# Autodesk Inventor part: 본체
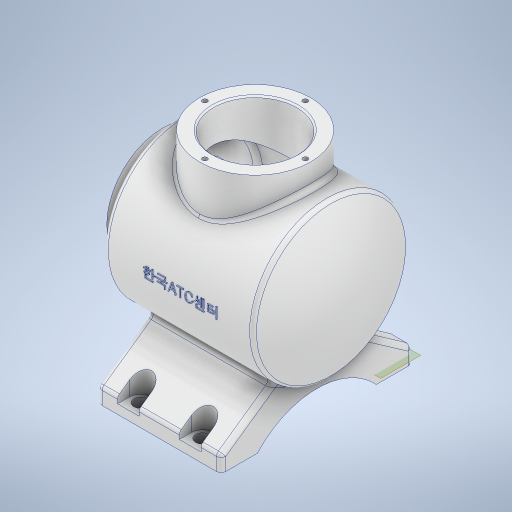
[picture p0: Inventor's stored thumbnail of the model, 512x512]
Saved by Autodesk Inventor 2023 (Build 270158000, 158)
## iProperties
Created: 2023-12
Part Number: 본체
Material: 알루미늄 6061
Document SubType Name: Modeling
Designer: asung
Mass: 1296.69 g
Surface Area: 1060.45 cm^2
Volume: 480.256 cm^3
Density: 2.7 g/cm^3
Appearance: 알루미늄 - 평지
Author: asung
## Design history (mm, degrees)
sketch "스케치1"
  geometry: L1 (60, 0)-(-60, 0); L2 (-60, 0)-(-60, 36); L3 (-60, 36)-(-48, 36); L4 (-48, 36)-(-48, 50); L5 (-48, 50)-(48.336, 50); L6 (-41, 43)-(43.887, 43); L7 (-41, 27)-(-41, 43); L8 (-60, 0)-(-60, 27); L9 (-60, 27)-(-41, 27); A1 r 113 centre (-53, 0) between (60, 0) and (48.336, 50); A2 r 106 centre (-53, 0) between (53, 0) and (43.887, 43); 2 further points
  constraints: 18 end point, 4 perpendicular, 4 point on circle, 2 centre point, 1 horizontal, 1 point on line, 1 vertical
  dimensions: "d3" = 120 distance of L1.start L1.end; "d4" = 36 distance of L1.end L2.end; "d5" = 12 distance of L2.end L3.end; "d6" = 14 distance of L3.end L4.end; "d13" = 7 distance between parallel lines of L5 L6; "d15" = 27 distance of L1.end L8.end; "d16" = 19 distance of L7.start L8.end
revolve "회전1" sketch "스케치1" stored, may be unused: angle "d17" = 360 deg
fillet "모깎기3" dims "d20" = 3
fillet "모깎기4" dims "d21" = 3
chamfer "모따기1" distance "d22" = 1; stored, may be unused: second distance "d23" = 2, angle "d24" = 45 deg
node "작업 평면1"
sketch "스케치2"
  geometry: C1 r 36 at (0, 0); 1 further point
  constraints: 1 centre point, 1 coincident
  dimensions: "d26" = 72 diameter of C1
extrude "돌출1" join sketch "스케치2" stored distance "d27" = 10; taper "d28" = 0 deg
fillet "모깎기5" dims "d29" = 3
sketch "스케치3"
  geometry: C1 r 27 at (0, 0); 1 further point
  constraints: 1 centre point, 1 coincident
  dimensions: "d30" = 54 diameter of C1
extrude "돌출2" cut sketch "스케치3" stored distance "d31" = 10; taper "d32" = 0 deg
chamfer "모따기2" distance "d33" = 1; stored, may be unused: second distance "d34" = 2, angle "d35" = 45 deg
sketch "스케치4" dims "d36" = 65
  geometry: 3 further points
  constraints: 1 coincident, 1 vertical alignment, 2 other
hole "구멍1" sketch "스케치4" at (0, 32.5) diameter "d37" = 3.242; stored, may be unused: countersink angle "d41" = 90 deg, drill point angle "d43" = 118 deg; dims "d38" = 8, "d39" = 4, "d40" = 2, "d42" = 10
sketch "스케치5" dims "d47" = 65
  geometry: 3 further points
  constraints: 1 coincident, 1 vertical alignment, 2 other
hole "구멍2" sketch "스케치5" at (0, 32.5) diameter "d48" = 3.242; stored, may be unused: countersink angle "d52" = 90 deg, drill point angle "d54" = 118 deg; dims "d49" = 8, "d50" = 4, "d51" = 2, "d53" = 10
sketch "스케치6"
  geometry: L1 (35.889, 36)-(65, 36) reference; L2 (65, 36)-(65, 34.121) reference; L3 (65, 34.121)-(55, 34.121) reference; L4 (55, 34.121)-(54.026, 32.5) reference; L5 (54.026, 32.5)-(55, 30.879) reference; L6 (55, 30.879)-(65, 30.879) reference; L7 (65, 30.879)-(65, 28) reference; L8 (65, 28)-(64, 27) reference; L9 (64, 27)-(33.466, 27) reference; L10 (33.466, -27)-(64, -27) reference; L11 (64, -27)-(65, -28) reference; L12 (65, -28)-(65, -30.879) reference; L13 (65, -30.879)-(55, -30.879) reference; L14 (55, -30.879)-(54.026, -32.5) reference; L15 (54.026, -32.5)-(55, -34.121) reference; L16 (55, -34.121)-(65, -34.121) reference; L17 (65, -34.121)-(65, -36) reference; L18 (65, -36)-(35.889, -36) reference; L19 (0, 0)-(-77, 0); L20 (-77, 0)-(-77, 38.5); L21 (-77, 38.5)-(-77, 62); L22 (-77, 62)-(-67, 62); L23 (-67, 62)-(-42.278, 26.694); L24 (-77, 0)-(-77, -38.5); L25 (-77, -38.5)-(-77, -62); L26 (-77, -62)-(-67, -62); L27 (-67, -62)-(-42.278, -26.694); A1 r 50 centre (0, 0) between (33.857, 36.792) and (33.857, -36.792) reference; A2 r 43 centre (0, 0) between (33.466, 27) and (33.466, -27) reference; A3 r 50 centre (0, 0) between (33.857, -36.792) and (33.857, 36.792) reference; A4 r 52.096 centre (-112.096, 0) between (-77, -38.5) and (-77, 38.5); 3 further points
  constraints: 18 end point, 5 point on circle, 3 perpendicular, 2 point on line, 1 centre point, 1 horizontal, 1 vertical, 2 other
  dimensions: "d58" = 77 distance of L19.start L19.end; "d59" = 38.5 distance of L19.end L20.end; "d60" = 38.5 distance of L19.end L24.end; "d61" = 10 distance of L25.end L26.end; "d62" = 17 horizontal distance of L20.end point (-60, 0); "d63" = 10 distance of L22.end L21.end; "d64" = 55 deg angle of L22 L23; "d65" = 55 deg angle of L26 L27; "d79" = 62 distance from line of L19.end L26; "d80" = 62 distance between parallel lines of L22 L19
extrude "돌출3" join sketch "스케치6" stored distance "d66" = 80; taper "d67" = 0 deg
fillet "모깎기6" dims "d68" = 3
fillet "모깎기7" dims "d69" = 3
fillet "모깎기8" dims "d70" = 3
sketch "스케치7"
  geometry: L1 (80, 97.5)-(80, 77) reference; L2 (80, 77)-(0, 77) reference; L3 (0, 77)-(0, 97.5) reference; L4 (3, 100.5)-(77, 100.5) reference; L5 (80, 0)-(80, -20.5) reference; L6 (77, -23.5)-(3, -23.5) reference; L7 (0, -20.5)-(0, 0) reference; L8 (0, 0)-(80, 0) reference; C1 r 4.5 at (20, -15.5); C2 r 4.5 at (20, 92.5); C3 r 4.5 at (60, 92.5); C4 r 4.5 at (60, -15.5); A1 r 3 centre (3, 97.5) between (3, 100.5) and (0, 97.5) reference; A2 r 3 centre (77, 97.5) between (80, 97.5) and (77, 100.5) reference; A3 r 3 centre (77, -20.5) between (77, -23.5) and (80, -20.5) reference; A4 r 3 centre (3, -20.5) between (0, -20.5) and (3, -23.5) reference; 1 further point
  constraints: 4 centre point
  dimensions: "d71" = 9 diameter of C1; "d72" = 20 distance from line of L7 C1.centre; "d76" = 20 distance from line of L3 C2.centre; "d81" = 108 distance of C2.centre C1.centre; "d82" = 8 distance from line of L4 C2.centre
extrude "돌출4" cut sketch "스케치7" stored distance "d83" = 80; taper "d84" = 0 deg
node "작업 평면2"
sketch "스케치8"
  geometry: L1 (80, 97.5)-(80, 70.517) reference; L2 (80, 70.517)-(0, 70.517) reference; L3 (0, 70.517)-(0, 97.5) reference; L4 (3, 100.5)-(77, 100.5) reference; L5 (80, 6.483)-(80, -20.5) reference; L6 (77, -23.5)-(3, -23.5) reference; L7 (0, -20.5)-(0, 6.483) reference; L8 (0, 6.483)-(80, 6.483) reference; L9 (13, 92.5)-(13, 105.537); L10 (27, 92.5)-(27, 111.612); L11 (53, 92.5)-(53, 114.449); L12 (67, 92.5)-(67, 116.315); L13 (13, -15.5)-(13, -37.217); L14 (88.336, -11.5)-(-8, -11.5) reference; L15 (27, -15.5)-(27, -37.217); L16 (53, -15.5)-(53, -36.443); L17 (67, -15.5)-(67, -42.796); C1 r 4.5 at (60, 92.5) reference; C2 r 4.5 at (20, -15.5) reference; C3 r 4.5 at (20, 92.5) reference; C4 r 4.5 at (60, -15.5) reference; C5 r 4.5 at (20, -15.5) reference; C6 r 4.5 at (60, -15.5) reference; C7 r 4.5 at (20, 92.5) reference; A1 r 3 centre (3, 97.5) between (3, 100.5) and (0, 97.5) reference; A2 r 3 centre (77, 97.5) between (80, 97.5) and (77, 100.5) reference; A3 r 3 centre (77, -20.5) between (77, -23.5) and (80, -20.5) reference; A4 r 3 centre (3, -20.5) between (0, -20.5) and (3, -23.5) reference; A5 r 7 centre (20, -15.5) between (13, -15.5) and (27, -15.5); A6 r 7 centre (60, -15.5) between (53, -15.5) and (67, -15.5); A7 r 7 centre (60, 92.5) between (53, 92.5) and (67, 92.5); A8 r 7 centre (20, 92.5) between (13, 92.5) and (27, 92.5); 9 further points
  constraints: 16 end point, 8 point on circle, 8 tangent, 6 vertical, 4 centre point, 4 coincident, 2 perpendicular
  dimensions: "d86" = 14 diameter of A5; "d87" = 14 diameter of A6; "d88" = 14 diameter of A7; "d89" = 14 diameter of A8
extrude "돌출5" cut sketch "스케치8" stored distance "d90" = 10; taper "d91" = 0 deg
node "작업 평면3"
fillet "모깎기9" dims "d92" = 3
sketch "스케치9"
  geometry: L1 (-60.168, 36)-(-60.168, -36) reference; 2 further points
  constraints: 1 horizontal alignment, 1 other
  dimensions: "d93" = 62 distance from line of L1 point (1.832, 0)
feature "엠보싱1" sketch "스케치9" dims "d3" = 120, "d4" = 36, "d5" = 12, "d6" = 14, "d13" = 7, "d15" = 27, "d16" = 19, "d23" = 2, "d94" = 0.5, "d95" = 0
node "솔리드1"
pattern_circular "원형 패턴1" dims angle "d45" = 360 deg
pattern_circular "원형 패턴2" dims angle "d56" = 360 deg
node "절단 모서리 투영1"
node "절단 모서리 투영2"
node "절단 모서리 투영3"
feature "A9D066F2-1C7D-4E18-AEED-F7BC21143FA4" dims "d37" = 3.242, "d38" = 8, "d39" = 4, "d40" = 2, "d41" = 90 deg, "d42" = 10, "d43" = 118 deg
other parameters: "d25" = 65, "d85" = -6
